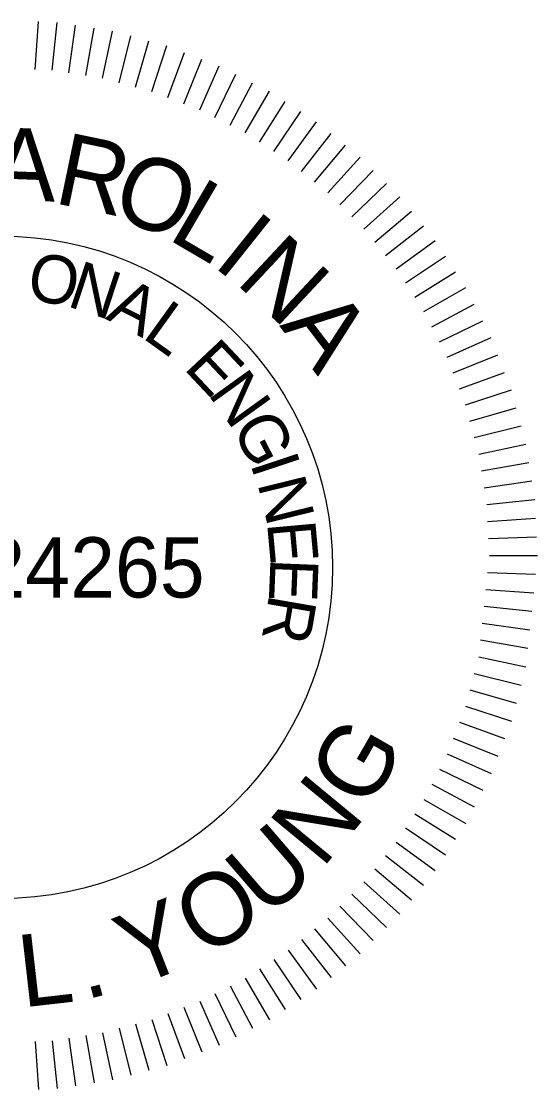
# Model space of a CAD drawing. Extents: x 1964849 to 1967422, y 1116563 to 1122210.
# Drawn here: x 1967361 to 1967399.1, y 1117096.3 to 1117175.2 of the extents above; entities that cross this region are included whole.
import ezdxf

# ---------------------------------------------------------------- set-up
doc = ezdxf.new("R2010")
doc.units = 0
doc.layers.add('RD_TX_PEShield', color=7, linetype='Continuous')

msp = doc.modelspace()

# ---------------------------------------------------------------- linework, layer by layer
at = {"layer": 'RD_TX_PEShield'}
for p, q in [((1967362.049, 1117171.641), (1967362.297, 1117175.188)), ((1967362.049, 1117171.641), (1967362.297, 1117175.188)), ((1967363.306, 1117171.575), (1967363.678, 1117175.115)), ((1967363.306, 1117171.575), (1967363.678, 1117175.115)), ((1967364.548, 1117171.378), (1967365.043, 1117174.899)), ((1967364.548, 1117171.378), (1967365.043, 1117174.899)), ((1967365.79, 1117171.182), (1967366.407, 1117174.683)), ((1967365.79, 1117171.182), (1967366.407, 1117174.683)), ((1967367.032, 1117170.985), (1967367.772, 1117174.467)), ((1967367.032, 1117170.985), (1967367.772, 1117174.467)), ((1967367.032, 1117170.985), (1967367.772, 1117174.467)), ((1967368.247, 1117170.659), (1967369.108, 1117174.109)), ((1967368.247, 1117170.659), (1967369.108, 1117174.109)), ((1967368.247, 1117170.659), (1967369.108, 1117174.109)), ((1967369.461, 1117170.334), (1967370.441, 1117173.752)), ((1967369.461, 1117170.334), (1967370.441, 1117173.752)), ((1967369.461, 1117170.334), (1967370.441, 1117173.752)), ((1967370.677, 1117170.008), (1967371.777, 1117173.394)), ((1967370.677, 1117170.008), (1967371.777, 1117173.394)), ((1967370.677, 1117170.008), (1967371.777, 1117173.394)), ((1967371.851, 1117169.557), (1967373.067, 1117172.899)), ((1967371.851, 1117169.557), (1967373.067, 1117172.899)), ((1967371.851, 1117169.557), (1967373.067, 1117172.899)), ((1967373.024, 1117169.107), (1967374.356, 1117172.404)), ((1967373.024, 1117169.107), (1967374.356, 1117172.404)), ((1967373.024, 1117169.107), (1967374.356, 1117172.404)), ((1967374.199, 1117168.656), (1967375.647, 1117171.908)), ((1967374.199, 1117168.656), (1967375.647, 1117171.908)), ((1967374.199, 1117168.656), (1967375.647, 1117171.908)), ((1967375.32, 1117168.085), (1967376.879, 1117171.281)), ((1967375.32, 1117168.085), (1967376.879, 1117171.281)), ((1967375.32, 1117168.085), (1967376.879, 1117171.281)), ((1967376.44, 1117167.514), (1967378.109, 1117170.654)), ((1967376.44, 1117167.514), (1967378.109, 1117170.654)), ((1967376.44, 1117167.514), (1967378.109, 1117170.654)), ((1967377.561, 1117166.943), (1967379.341, 1117170.026)), ((1967377.561, 1117166.943), (1967379.341, 1117170.026)), ((1967377.561, 1117166.943), (1967379.341, 1117170.026)), ((1967378.616, 1117166.258), (1967380.5, 1117169.273)), ((1967378.616, 1117166.258), (1967380.5, 1117169.273)), ((1967378.616, 1117166.258), (1967380.5, 1117169.273)), ((1967379.67, 1117165.574), (1967381.658, 1117168.521)), ((1967379.67, 1117165.574), (1967381.658, 1117168.521)), ((1967379.67, 1117165.574), (1967381.658, 1117168.521)), ((1967380.725, 1117164.888), (1967382.817, 1117167.769)), ((1967380.725, 1117164.888), (1967382.817, 1117167.769)), ((1967380.725, 1117164.888), (1967382.817, 1117167.769)), ((1967381.703, 1117164.097), (1967383.892, 1117166.899)), ((1967381.703, 1117164.097), (1967383.892, 1117166.899)), ((1967381.703, 1117164.097), (1967383.892, 1117166.899)), ((1967382.679, 1117163.306), (1967384.965, 1117166.03)), ((1967382.679, 1117163.306), (1967384.965, 1117166.03)), ((1967382.679, 1117163.306), (1967384.965, 1117166.03)), ((1967383.657, 1117162.514), (1967386.039, 1117165.16)), ((1967383.657, 1117162.514), (1967386.039, 1117165.16)), ((1967383.657, 1117162.514), (1967386.039, 1117165.16)), ((1967384.546, 1117161.624), (1967387.016, 1117164.182)), ((1967384.546, 1117161.624), (1967387.016, 1117164.182)), ((1967384.546, 1117161.624), (1967387.016, 1117164.182)), ((1967385.435, 1117160.736), (1967387.993, 1117163.206)), ((1967385.435, 1117160.736), (1967387.993, 1117163.206)), ((1967385.435, 1117160.736), (1967387.993, 1117163.206)), ((1967386.325, 1117159.846), (1967388.97, 1117162.228)), ((1967386.325, 1117159.846), (1967388.97, 1117162.228)), ((1967386.325, 1117159.846), (1967388.97, 1117162.228)), ((1967387.116, 1117158.868), (1967389.84, 1117161.154)), ((1967387.116, 1117158.868), (1967389.84, 1117161.154)), ((1967387.116, 1117158.868), (1967389.84, 1117161.154)), ((1967387.907, 1117157.892), (1967390.709, 1117160.081)), ((1967387.907, 1117157.892), (1967390.709, 1117160.081)), ((1967387.907, 1117157.892), (1967390.709, 1117160.081)), ((1967388.699, 1117156.914), (1967391.579, 1117159.007)), ((1967388.699, 1117156.914), (1967391.579, 1117159.007)), ((1967388.699, 1117156.914), (1967391.579, 1117159.007)), ((1967389.384, 1117155.859), (1967392.332, 1117157.847)), ((1967389.384, 1117155.859), (1967392.332, 1117157.847)), ((1967389.384, 1117155.859), (1967392.332, 1117157.847)), ((1967390.069, 1117154.805), (1967393.084, 1117156.689)), ((1967390.069, 1117154.805), (1967393.084, 1117156.689)), ((1967390.069, 1117154.805), (1967393.084, 1117156.689)), ((1967390.754, 1117153.75), (1967393.837, 1117155.53)), ((1967390.754, 1117153.75), (1967393.837, 1117155.53)), ((1967390.754, 1117153.75), (1967393.837, 1117155.53)), ((1967391.325, 1117152.629), (1967394.465, 1117154.298)), ((1967391.325, 1117152.629), (1967394.465, 1117154.298)), ((1967391.325, 1117152.629), (1967394.465, 1117154.298)), ((1967391.896, 1117151.509), (1967395.091, 1117153.068)), ((1967391.896, 1117151.509), (1967395.091, 1117153.068)), ((1967391.896, 1117151.509), (1967395.091, 1117153.068)), ((1967392.467, 1117150.388), (1967395.719, 1117151.836)), ((1967392.467, 1117150.388), (1967395.719, 1117151.836)), ((1967392.467, 1117150.388), (1967395.719, 1117151.836)), ((1967392.918, 1117149.214), (1967396.214, 1117150.546)), ((1967392.918, 1117149.214), (1967396.214, 1117150.546)), ((1967392.918, 1117149.214), (1967396.214, 1117150.546)), ((1967393.368, 1117148.041), (1967396.709, 1117149.257)), ((1967393.368, 1117148.041), (1967396.709, 1117149.257)), ((1967393.368, 1117148.041), (1967396.709, 1117149.257)), ((1967393.819, 1117146.866), (1967397.205, 1117147.966)), ((1967393.819, 1117146.866), (1967397.205, 1117147.966)), ((1967393.819, 1117146.866), (1967397.205, 1117147.966)), ((1967394.145, 1117145.651), (1967397.562, 1117146.631)), ((1967394.145, 1117145.651), (1967397.562, 1117146.631)), ((1967394.145, 1117145.651), (1967397.562, 1117146.631)), ((1967394.47, 1117144.437), (1967397.92, 1117145.297)), ((1967394.47, 1117144.437), (1967397.92, 1117145.297)), ((1967394.47, 1117144.437), (1967397.92, 1117145.297)), ((1967394.795, 1117143.222), (1967398.278, 1117143.962)), ((1967394.795, 1117143.222), (1967398.278, 1117143.962)), ((1967394.795, 1117143.222), (1967398.278, 1117143.962)), ((1967394.992, 1117141.979), (1967398.494, 1117142.596)), ((1967394.992, 1117141.979), (1967398.494, 1117142.596)), ((1967394.992, 1117141.979), (1967398.494, 1117142.596)), ((1967395.189, 1117140.738), (1967398.71, 1117141.233)), ((1967395.189, 1117140.738), (1967398.71, 1117141.233)), ((1967395.189, 1117140.738), (1967398.71, 1117141.233)), ((1967395.386, 1117139.495), (1967398.926, 1117139.867)), ((1967395.386, 1117139.495), (1967398.926, 1117139.867)), ((1967395.386, 1117139.495), (1967398.926, 1117139.867)), ((1967395.451, 1117138.239), (1967398.998, 1117138.487)), ((1967395.451, 1117138.239), (1967398.998, 1117138.487)), ((1967395.451, 1117138.239), (1967398.998, 1117138.487)), ((1967395.517, 1117136.984), (1967399.071, 1117137.108)), ((1967395.517, 1117136.984), (1967399.071, 1117137.108)), ((1967395.517, 1117136.984), (1967399.071, 1117137.108)), ((1967395.583, 1117135.727), (1967399.143, 1117135.727)), ((1967395.583, 1117135.727), (1967399.143, 1117135.727)), ((1967395.583, 1117135.727), (1967399.143, 1117135.727)), ((1967395.451, 1117134.473), (1967398.998, 1117134.349)), ((1967395.451, 1117134.473), (1967398.998, 1117134.349)), ((1967395.32, 1117133.225), (1967398.854, 1117132.978)), ((1967395.32, 1117133.225), (1967398.854, 1117132.978)), ((1967395.189, 1117131.98), (1967398.71, 1117131.61)), ((1967395.189, 1117131.98), (1967398.71, 1117131.61)), ((1967395.058, 1117130.735), (1967398.567, 1117130.242)), ((1967395.058, 1117130.735), (1967398.567, 1117130.242)), ((1967394.927, 1117129.487), (1967398.422, 1117128.871)), ((1967394.927, 1117129.487), (1967398.422, 1117128.871)), ((1967394.795, 1117128.233), (1967398.278, 1117127.493)), ((1967394.795, 1117128.233), (1967398.278, 1117127.493)), ((1967394.47, 1117127.018), (1967397.92, 1117126.158)), ((1967394.47, 1117127.018), (1967397.92, 1117126.158)), ((1967394.145, 1117125.804), (1967397.562, 1117124.824)), ((1967394.145, 1117125.804), (1967397.562, 1117124.824)), ((1967393.819, 1117124.589), (1967397.205, 1117123.489)), ((1967393.819, 1117124.589), (1967397.205, 1117123.489)), ((1967393.368, 1117123.414), (1967396.709, 1117122.198)), ((1967393.368, 1117123.414), (1967396.709, 1117122.198)), ((1967392.918, 1117122.241), (1967396.214, 1117120.909)), ((1967392.918, 1117122.241), (1967396.214, 1117120.909)), ((1967392.467, 1117121.067), (1967395.719, 1117119.619)), ((1967392.467, 1117121.067), (1967395.719, 1117119.619)), ((1967391.896, 1117119.946), (1967395.091, 1117118.387)), ((1967391.896, 1117119.946), (1967395.091, 1117118.387)), ((1967391.325, 1117118.826), (1967394.465, 1117117.157)), ((1967391.325, 1117118.826), (1967394.465, 1117117.157)), ((1967390.754, 1117117.705), (1967393.837, 1117115.925)), ((1967390.754, 1117117.705), (1967393.837, 1117115.925)), ((1967390.069, 1117116.65), (1967393.084, 1117114.766)), ((1967390.069, 1117116.65), (1967393.084, 1117114.766)), ((1967389.384, 1117115.596), (1967392.332, 1117113.608)), ((1967389.384, 1117115.596), (1967392.332, 1117113.608)), ((1967388.699, 1117114.541), (1967391.579, 1117112.448)), ((1967388.699, 1117114.541), (1967391.579, 1117112.448)), ((1967387.907, 1117113.563), (1967390.709, 1117111.374)), ((1967387.907, 1117113.563), (1967390.709, 1117111.374)), ((1967387.116, 1117112.586), (1967389.84, 1117110.301)), ((1967387.116, 1117112.586), (1967389.84, 1117110.301)), ((1967386.325, 1117111.609), (1967388.97, 1117109.227)), ((1967386.325, 1117111.609), (1967388.97, 1117109.227)), ((1967385.435, 1117110.719), (1967387.993, 1117108.249)), ((1967385.435, 1117110.719), (1967387.993, 1117108.249)), ((1967384.546, 1117109.83), (1967387.016, 1117107.273)), ((1967384.546, 1117109.83), (1967387.016, 1117107.273)), ((1967383.657, 1117108.941), (1967386.039, 1117106.295)), ((1967382.679, 1117108.149), (1967384.965, 1117105.425)), ((1967382.679, 1117108.149), (1967384.965, 1117105.425)), ((1967381.703, 1117107.358), (1967383.892, 1117104.556)), ((1967381.703, 1117107.358), (1967383.892, 1117104.556)), ((1967380.725, 1117106.566), (1967382.817, 1117103.686)), ((1967380.725, 1117106.566), (1967382.817, 1117103.686)), ((1967379.67, 1117105.881), (1967381.658, 1117102.933)), ((1967379.67, 1117105.881), (1967381.658, 1117102.933)), ((1967378.616, 1117105.197), (1967380.5, 1117102.181)), ((1967378.616, 1117105.197), (1967380.5, 1117102.181)), ((1967376.44, 1117103.94), (1967378.109, 1117100.801)), ((1967376.44, 1117103.94), (1967378.109, 1117100.801)), ((1967377.561, 1117104.512), (1967379.341, 1117101.428)), ((1967377.561, 1117104.512), (1967379.341, 1117101.428)), ((1967375.32, 1117103.37), (1967376.879, 1117100.174)), ((1967375.32, 1117103.37), (1967376.879, 1117100.174)), ((1967373.024, 1117102.348), (1967374.356, 1117099.051)), ((1967373.024, 1117102.348), (1967374.356, 1117099.051)), ((1967374.199, 1117102.799), (1967375.647, 1117099.546)), ((1967374.199, 1117102.799), (1967375.647, 1117099.546)), ((1967371.851, 1117101.897), (1967373.067, 1117098.556)), ((1967371.851, 1117101.897), (1967373.067, 1117098.556)), ((1967368.247, 1117100.796), (1967369.108, 1117097.346)), ((1967368.247, 1117100.796), (1967369.108, 1117097.346)), ((1967369.461, 1117101.121), (1967370.441, 1117097.703)), ((1967369.461, 1117101.121), (1967370.441, 1117097.703)), ((1967370.677, 1117101.447), (1967371.777, 1117098.061)), ((1967370.677, 1117101.447), (1967371.777, 1117098.061)), ((1967364.548, 1117100.077), (1967365.043, 1117096.556)), ((1967364.548, 1117100.077), (1967365.043, 1117096.556)), ((1967365.79, 1117100.273), (1967366.407, 1117096.772)), ((1967365.79, 1117100.273), (1967366.407, 1117096.772)), ((1967367.032, 1117100.47), (1967367.772, 1117096.988)), ((1967367.032, 1117100.47), (1967367.772, 1117096.988)), ((1967362.049, 1117099.814), (1967362.297, 1117096.267)), ((1967362.049, 1117099.814), (1967362.297, 1117096.267)), ((1967363.306, 1117099.88), (1967363.678, 1117096.339)), ((1967363.306, 1117099.88), (1967363.678, 1117096.339))]:
    msp.add_line(p, q, dxfattribs=at)
msp.add_circle((1967359.538, 1117134.849), 24.475, dxfattribs=at)

# ---------------------------------------------------------------- texts
for s, height, rotation, p in [('A', 5.34, 357.94482, (1967358.747, 1117162.04)), ('R', 5.34, 348.26699, (1967363.33, 1117161.786)), ('O', 5.34, 339.32858, (1967367.469, 1117160.87)), ('L', 5.34, 329.65075, (1967371.73, 1117159.166)), ('I', 5.34, 321.46627, (1967375.068, 1117157.183)), ('N', 5.34, 317.00069, (1967376.76, 1117155.906)), ('O', 3.56, 350.40454, (1967361.337, 1117154.674)), ('N', 3.56, 341.70291, (1967364.316, 1117154.174)), ('A', 3.56, 333.00129, (1967367.184, 1117153.228)), ('L', 3.56, 324.29966, (1967369.877, 1117151.86)), ('A', 5.34, 307.32286, (1967380.054, 1117152.711)), ('E', 3.56, 313.22511, (1967372.952, 1117149.557)), ('N', 3.56, 305.73175, (1967374.755, 1117147.682)), ('G', 3.56, 297.03012, (1967376.522, 1117145.232)), ('I', 3.56, 288.3285, (1967377.897, 1117142.544)), ('N', 3.56, 283.84405, (1967378.442, 1117141.085)), ('E', 3.56, 275.14243, (1967379.168, 1117138.153)), ('E', 3.56, 267.64906, (1967379.431, 1117135.565)), ('R', 3.56, 260.15569, (1967379.355, 1117132.964)), ('G', 5.34, 60.11131, (1967386.647, 1117116.826)), ('N', 5.34, 50.43348, (1967383.232, 1117112.525)), ('U', 5.34, 40.75564, (1967379.141, 1117108.86)), ('O', 5.34, 31.07781, (1967374.493, 1117105.934)), ('Y', 5.34, 21.39998, (1967369.42, 1117103.831)), ('L', 5.34, 6.51713, (1967361.121, 1117102.334)), ('.', 5.34, 14.70161, (1967365.734, 1117102.891))]:
    msp.add_text(s, height=height, rotation=rotation, dxfattribs=at).set_placement(p)
msp.add_text('NO. 24265', height=4.4501, dxfattribs=at).set_placement((1967345.784, 1117132.624))

doc.saveas('drawing.dxf')
